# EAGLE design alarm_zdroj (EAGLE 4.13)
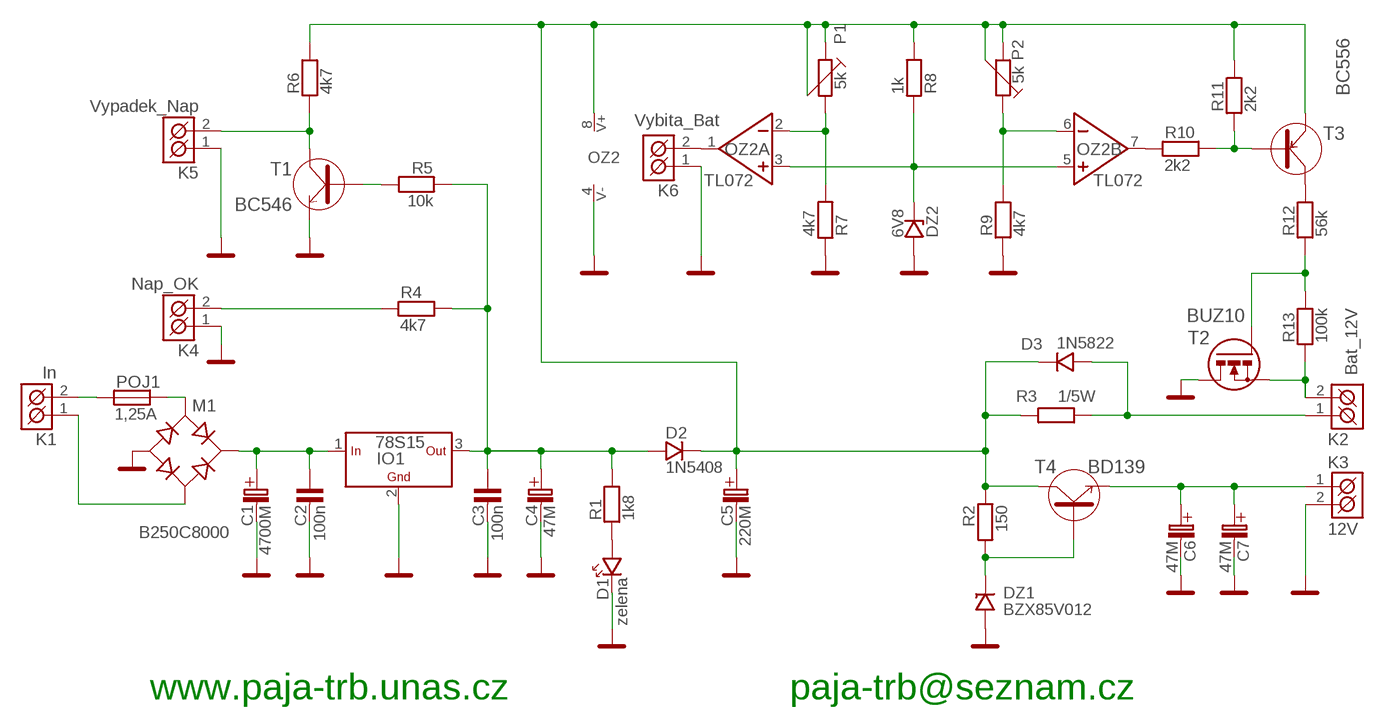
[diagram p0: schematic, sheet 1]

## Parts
C1  4700M  2200M/35V  [C_EL_7,5]
C2  100n  C-KERAMIK_5  [C-5]
C3  100n  C-KERAMIK_5  [C-5]
C4  47M  47M/25V  [C_EL_2]
C5  220M  220M/25V  [C_EL_3,5]
C6  47M  47M/25V  [C_EL_2]
C7  47M  47M/25V  [C_EL_2]
D1  zelena  LED_5  [LED_5]
D2  1N5408  [D-12,7]
D3  1N5822  1N5408  [D-12,7]
DZ1  BZX85V012  D-ZENEROVA_2W_BZY  [D-10]
DZ2  6V8  D-ZENEROVA_0,5W_BZX83V  [D-7,5]
IO1  78S15  78_STOJ_STOJ  [TO-220S]
K1  In  CZM_5/2  [CZM_5/2]
K2  Bat_12V  CZM_5/2  [CZM_5/2]
K3  12V  CZM_5/2  [CZM_5/2]
K4  Nap_OK  CZM_5/2  [CZM_5/2]
K5  Vypadek_Nap  CZM_5/2  [CZM_5/2]
K6  Vybita_Bat  CZM_5/2  [CZM_5/2]
M1  B250C8000  [DM_KBU]
OZ2  TL072  [DIL8]
P1  5k  PT-10_V-LEZ  [PT10V]
P2  5k  PT-10_V-LEZ  [PT10V]
POJ1  1,25A  PO_SHH  [POJ_SHH]
R1  1k8  R_7,5  [R-7,5]
R2  150  R_7,5  [R-7,5]
R3  1/5W  R__5W  [R-_5W]
R4  4k7  R_7,5  [R-7,5]
R5  10k  R_7,5  [R-7,5]
R6  4k7  R_7,5  [R-7,5]
R7  4k7  R_7,5  [R-7,5]
R8  1k  R_7,5  [R-7,5]
R9  4k7  R_7,5  [R-7,5]
R10  2k2  R_7,5  [R-7,5]
R11  2k2  R_7,5  [R-7,5]
R12  56k  R_7,5  [R-7,5]
R13  100k  R_7,5  [R-7,5]
T1  BC546  [TO-92]
T2  BUZ10  BUZ10_STOJ  [TO-220S]
T3  BC556  [TO-92]
T4  BD139  [TO-126S]

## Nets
12V: C6.C+(C_EL+) C7.C+(C_EL+) K3.1(K1) T4.1(E)
15V: C3.1 C4.C+(C_EL+) D2.A IO1.3(OUT) R1.2 R4.2 R5.1
+BAT: C5.C+(C_EL+) D2.K D3.K OZ2.8(NS:V+) P1.1 P1.3 P2.2 P2.3 R2.1 R3.1 R6.2 R8.2 R11.2 T3.3(E) T4.2(C)
GND: C1.C-(C_EL-) C2.2 C3.2 C4.C-(C_EL-) C5.C-(C_EL-) C6.C-(C_EL-) C7.C-(C_EL-) D1.K DZ1.A DZ2.A IO1.2(GND) K3.2(K2) K4.1(K1) K5.1(K1) K6.1(K1) M1.- OZ2.4(NS:V-) R7.1 R9.1 T1.3(E) T2.2(D)
GND_BAT: K2.2(K2) R13.1 T2.3(S)
N$1: K1.2(K2) POJ1.L1
N$2: K1.1(K1) M1.AC2
N$3: C1.C+(C_EL+) C2.1 IO1.1(IN) M1.+
N$4: D3.A K2.1(K1) R3.2
N$5: D1.A R1.1
N$6: R5.2 T1.2(B)
N$7: K4.2(K2) R4.1
N$8: K5.2(K2) R6.1 T1.1(C)
N$9: M1.AC1 POJ1.P1
N$10: DZ1.K R2.2 T4.3(B)
N$13: R12.1 R13.2 T2.1(G)
N$14: DZ2.K OZ2.3(A:NEIN+) OZ2.5(B:NEIN+) R8.1
N$15: OZ2.2(A:IN-) P1.2 R7.2
N$16: OZ2.7(B:VYSTUP) R10.1
N$17: K6.2(K2) OZ2.1(A:VYSTUP)
N$18: R10.2 R11.1 T3.2(B)
N$20: R12.2 T3.1(C)
N$22: OZ2.6(B:IN-) P2.1 R9.2

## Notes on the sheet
- www.paja-trb.unas.cz | paja-trb@seznam.cz

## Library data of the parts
C1 = #PaJa_C-el:2200M/35V
C2 C3 = #PaJa_13:C-KERAMIK: Kondenzator - keramicky
C4 C6 C7 = #PaJa_C-el:47M/25V
C5 = #PaJa_C-el:220M/25V
D1 = #PaJa_13:LED: LED - jednobarevna
D2 D3 = #PaJa_13:1N5408: Usmernovaci dioda - 3A, 1000V
DZ1 DZ2 = #PaJa_13:D-ZENEROVA: Zenerova dioda
IO1 = #PaJa_13:78??: Stabilizátor - 1A a 1,5A ?? - napeti => 05, 06, 08, 09, 12, 15, 18, 20, 24 => 1,5A ?? - napeti => 10, 12, 15, 18 => 1A
K1-K6 = #PaJa_14:CZM_5/2: Svorkovnice - roztec 5,08mm - dvojita
M1 = #PaJa_15:B250C8000: Diodovy mustek - 250V, 8A
OZ2 = #PaJa_14:TL072: OZ - JFET - 2x
P1 = #PaJa_13:PT-10: Trimr - 10,3mm
P2 = #PaJa_14:PT-10: Trimr - 10,3mm
POJ1 = #PaJa_14:PO_SHH: Pojistkove pouzdro
R1 R5-R8 = #PaJa_13:R: Rezistor
R2 R3 = #PaJa_15:R: Rezistor
R4 R9-R13 = #PaJa_14:R: Rezistor
T1 = #PaJa_13:BC546: Tranzistor NPN - Univerzalni NF - Ic=0,1A
T2 = #PaJa_14:BUZ10: N-Channel Enhancement MOSFET 50V; 20A; 0,080Ohm
T3 = #PaJa_14:BC556: Tranzistor PNP - Univerzalni NF - Ic=0,1A
T4 = #PaJa_15:BD139: Tranzistor NPN - Vykonovy - Ic=1,5A

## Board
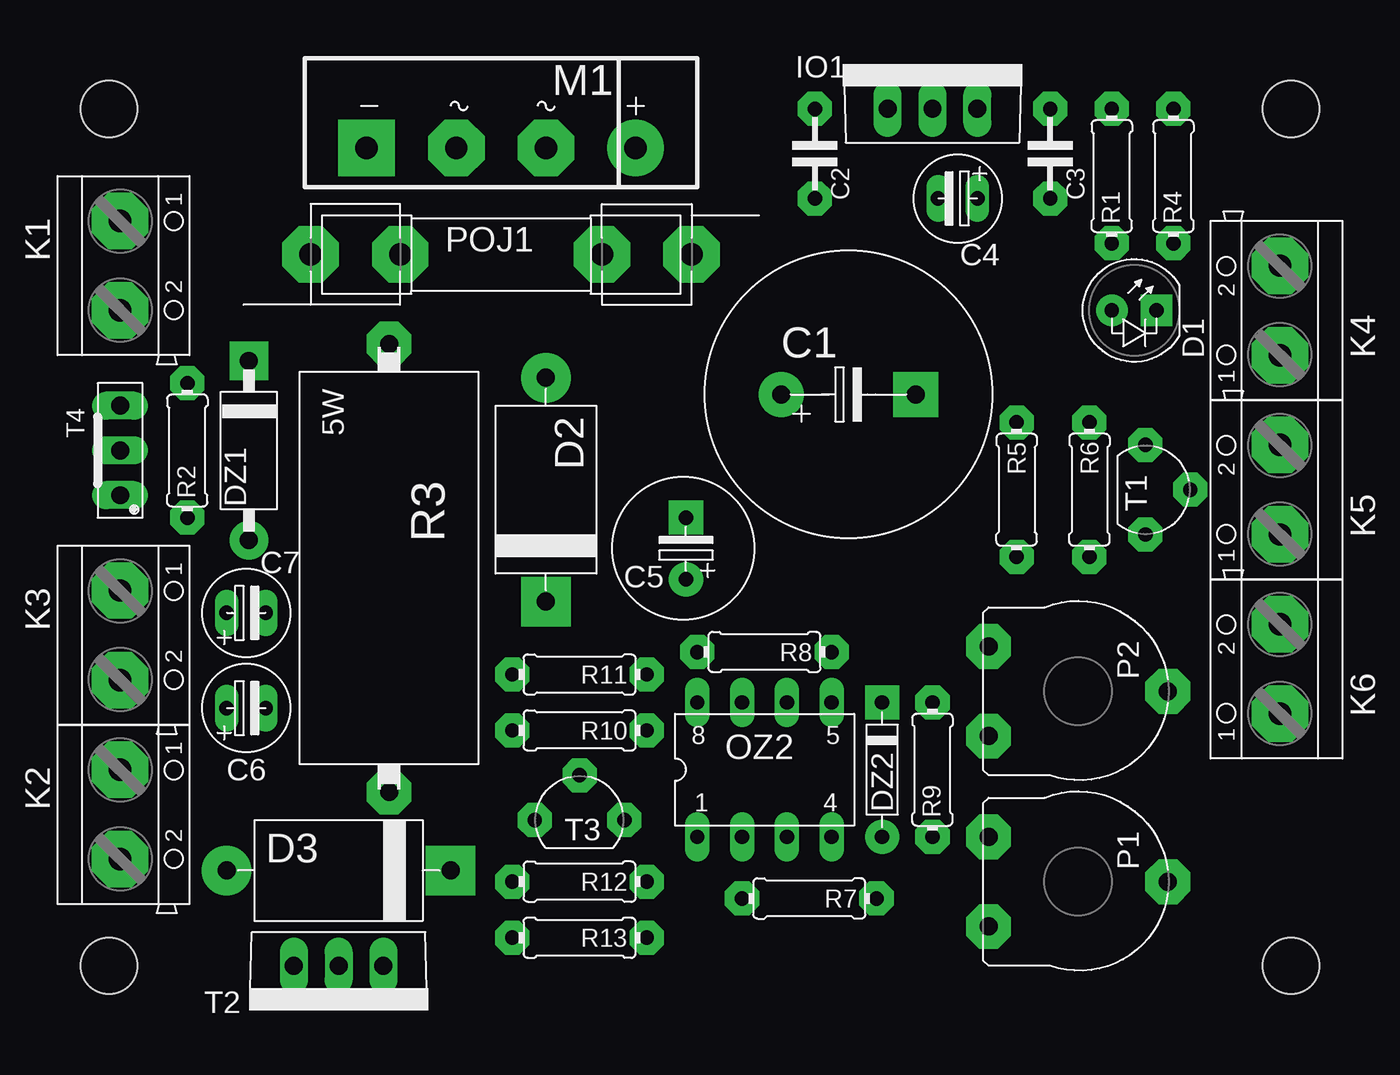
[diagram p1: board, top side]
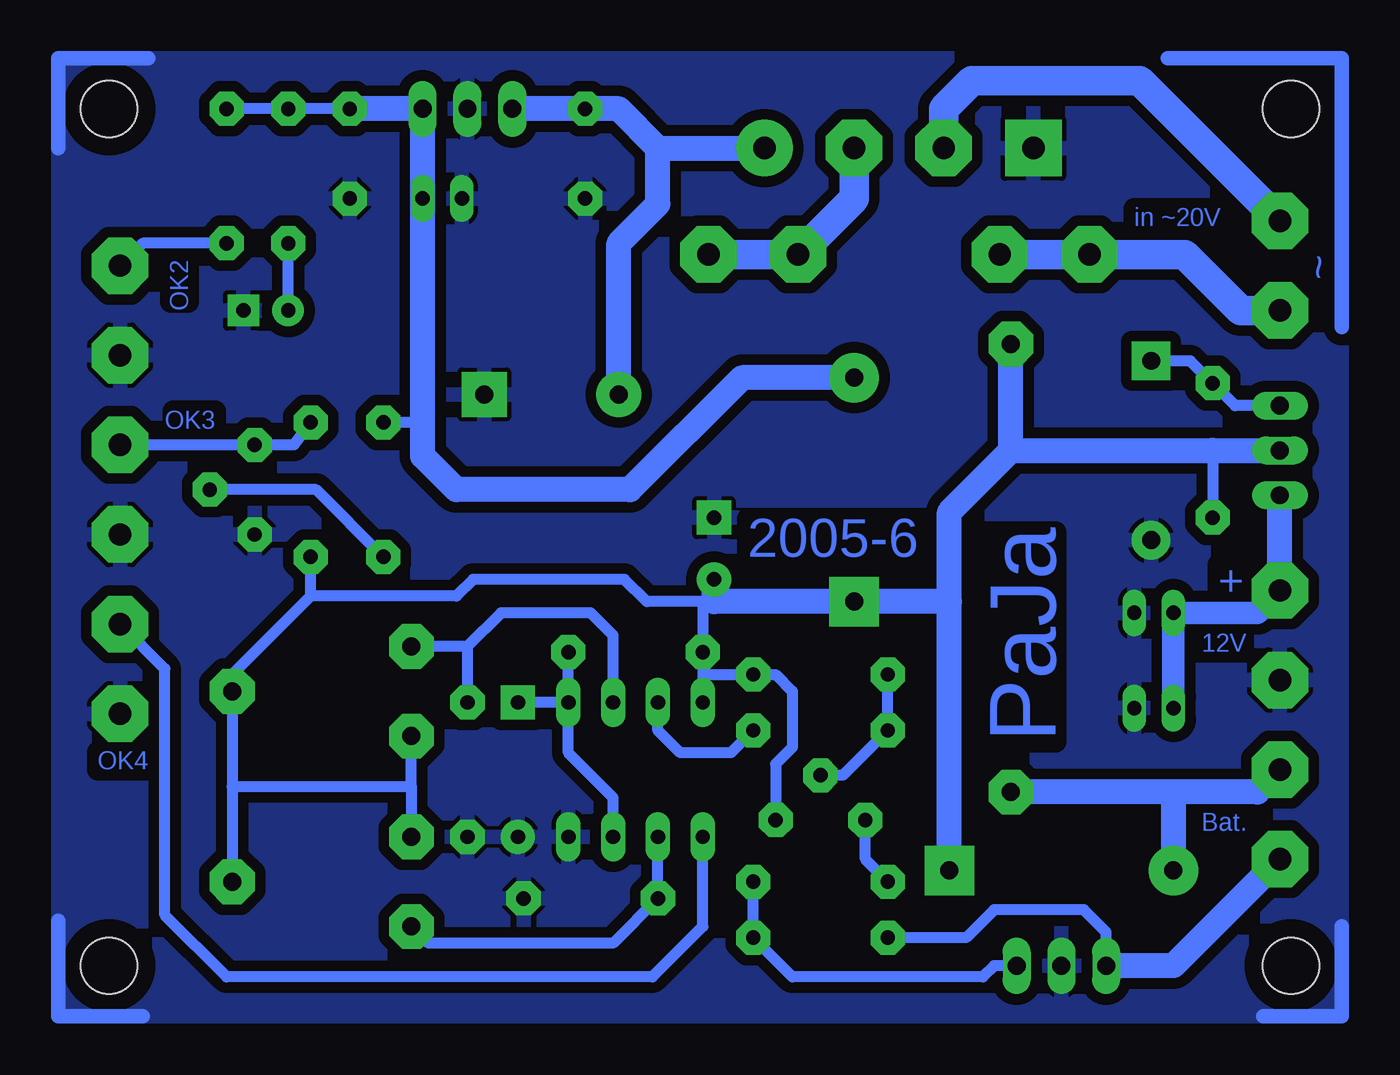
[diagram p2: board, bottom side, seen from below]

No outline drawn. Coordinates in mm, seen from the top.
Copper layers (1*16): Top 0.035mm / dielectric 1.5mm / Bottom 0.035mm
Design rules "default": minimum track width 10mil, minimum drill 24mil, track to track 8mil, track to pad 8mil, pad to pad 8mil, via to via 8mil, smd to smd 8mil, copper to edge 40mil, drill to drill 8mil, minimum pad ring 10mil, minimum via ring 8mil, stop-mask expansion 4mil, vias tented up to drill 0mil, thermal gap 10mil
Holes 3.2 mm at 6.67,13.02 6.67,61.59 73.66,61.59 73.66,13.02

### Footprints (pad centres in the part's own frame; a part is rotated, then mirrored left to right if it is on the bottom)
C_EL_7,5 = drill 1.016 pad 2.54 round: C+ -3.81,0 | drill 1.016 pad 2.54 square: C- 3.81,0
C-5 = drill 0.813 pad 1.93 octagon: 1 -2.54,0; 2 2.54,0
C_EL_2 = drill 0.813 pad 1.27 long: C+ 0,0; C- 2.223,0
C_EL_3,5 = drill 0.813 pad 1.93 round: C+ 0,0 | drill 0.813 pad 1.93 square: C- 3.493,0
LED_5 = drill 0.813 pad 1.778 round: A -1.27,0 | drill 0.813 pad 1.778 square: K 1.27,0
D-12,7 = drill 1.016 pad 2.8 round: A -6.35,0 | drill 1.016 pad 2.8 square: K 6.35,0
D-10 = drill 1.016 pad 2.184 round: A -5.08,0 | drill 1.016 pad 2.184 square: K 5.08,0
D-7,5 = drill 0.813 pad 1.93 round: A -3.81,0 | drill 0.813 pad 1.93 square: K 3.81,0
TO-220S = drill 1.016 pad 1.6 long: 1 -2.54,0; 2 0,0; 3 2.54,0
CZM_5/2 = drill 1.27 pad 3.2 octagon: 1 -2.54,0; 2 2.54,0
DM_KBU = drill 1.27 pad 3.2 round: + -7.62,2.857 | drill 1.27 pad 3.2 square: - 7.62,2.857 | drill 1.27 pad 3.2 octagon: AC1 -2.54,2.857; AC2 2.54,2.857
DIL8 = drill 0.813 pad 1.4 long: 1 -3.81,-3.81; 2 -1.27,-3.81; 3 1.27,-3.81; 4 3.81,-3.81; 5 3.81,3.81; 6 1.27,3.81; 7 -1.27,3.81; 8 -3.81,3.81
PT10V = drill 1.016 pad 2.54 octagon: 1 -2.54,-5.08; 2 2.54,-5.08; 3 0,5.08
POJ_SHH = drill 1.27 pad 3.2 octagon: L1 -10.795,0; L2 -5.715,0; P1 10.795,0; P2 5.715,0
R-7,5 = drill 0.813 pad 1.93 octagon: 1 -3.81,0; 2 3.81,0
R-_5W = drill 1.016 pad 2.54 octagon: 1 -12.7,0; 2 12.7,0
TO-92 = drill 0.813 pad 1.93 octagon: 1 0,2.54; 2 2.54,0; 3 0,-2.54
TO-126S = drill 1.016 pad 1.6 long: 1 -2.54,0; 2 0,0; 3 2.54,0

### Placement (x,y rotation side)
C1  48.58,45.4 0 top
C2  46.67,59.05 270 top
C3  60.01,59.05 270 top
C4  55.88,56.52 180 top
C5  39.37,34.92 90 top
C6  13.34,27.62 0 top
C7  13.34,33.02 0 top
D1  64.77,50.16 0 top
D2  31.43,40.01 270 top
D3  19.68,18.41 0 top
DZ1  14.61,42.23 90 top
DZ2  50.48,24.13 90 top
IO1  53.34,61.59 0 top
K1  7.3,52.7 270 top
K2  7.3,21.59 270 top
K3  7.3,31.75 270 top
K4  73.03,50.16 90 top
K5  73.03,40.01 90 top
K6  73.03,29.84 90 top
M1  28.89,62.23 180 top
OZ2  43.81,24.13 0 top
P1  61.59,17.78 270 top
P2  61.59,28.57 270 top
POJ1  28.89,53.34 0 top
R1  63.5,57.78 90 top
R2  11.11,42.23 90 top
R3  22.54,35.56 270 top
R4  66.99,57.78 90 top
R5  58.1,40.01 270 top
R6  62.23,40.01 270 top
R7  46.35,16.83 180 top
R8  43.81,30.8 180 top
R9  53.34,24.13 90 top
R10  33.34,26.35 180 top
R11  33.34,29.53 0 top
R12  33.34,17.78 180 top
R13  33.34,14.61 0 top
T1  65.41,40.01 0 top
T2  19.68,13.02 180 top
T3  33.34,21.27 90 top
T4  7.3,42.23 90 top

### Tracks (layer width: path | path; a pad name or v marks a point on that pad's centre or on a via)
12V
  Bottom 1.27: C6.C+ C7.C+ 8.57,33.02 K3.1
  Bottom 1.422: K3.1 T4.1
15V
  Bottom 0.61: R4.2 R1.2 C3.1 | 55.88,43.81 R5.1
  Bottom 1.422: C3.1 IO1.3 C4.C+ 55.88,43.81 55.88,41.91 53.98,40.01 44.13,40.01 37.78,46.35 D2.A
+BAT
  Bottom 0.61: 66.67,23.18 P2.3 66.67,29.53 62.23,33.97 | 66.67,23.18 P1.3 | 66.67,23.18 56.52,23.18 | 56.52,23.18 P2.2 | 56.52,23.18 P1.1 | T3.3 35.88,24.45 34.92,25.4 34.92,28.57 35.88,29.53 R11.2 40.01,29.53 | 62.23,33.97 53.98,33.97 53.02,34.92 44.45,34.92 43.18,33.66 40.01,33.66 | 62.23,33.97 R6.2 | 11.11,42.23 R2.1 | 39.37,33.66 40.01,33.66 | 40.01,33.66 R8.2 40.01,29.53 | 40.01,29.53 OZ2.8
  Bottom 1.422: 22.54,42.23 11.11,42.23 T4.2 | 22.54,42.23 R3.1 | 26.04,33.66 D2.K 39.37,33.66 C5.C+ | D3.K 26.04,33.66 | 26.04,33.66 26.04,38.73 22.54,42.23
GND
  Bottom 0.813: 71.44,64.45 76.52,64.45 76.52,59.37 | 71.75,10.16 76.52,10.16 76.52,15.56 | 3.81,15.24 3.81,10.16 8.26,10.16
  pour Bottom (isolate 0.61): 3.81,64.45 3.81,10.16 76.52,10.16 76.52,64.45
GND_BAT
  Bottom 0.61: T2.3 17.14,14.92 18.41,16.19 23.5,16.19 25.08,14.61 R13.1
  Bottom 1.422: K2.2 13.34,13.02 T2.3
N$1
  Bottom 1.676: K1.2 9.53,50.16 12.7,53.34 POJ1.L1 23.18,53.34
N$2
  Bottom 1.676: K1.1 15.24,63.18 24.77,63.18 26.35,61.59 M1.AC2
N$3
  Bottom 1.422: IO1.1 C2.1 44.77,61.59 42.55,59.37 | 42.55,59.37 M1.+ | C1.C+ 44.77,53.98 42.55,56.2 42.55,59.37
N$4
  Bottom 1.422: 13.34,22.86 R3.2 | 13.34,22.86 D3.A | K2.1 8.57,22.86 13.34,22.86
N$5
  Bottom 0.61: D1.A R1.1
N$6
  Bottom 0.61: R5.2 61.91,40.01 T1.2
N$7
  Bottom 0.61: R4.1 71.75,53.98 K4.2
N$8
  Bottom 0.61: R6.1 63.18,42.55 T1.1 K5.2
N$9
  Bottom 1.676: POJ1.P1 34.61,53.34 31.43,56.52 M1.AC1
N$10
  Bottom 0.61: T4.3 9.84,44.77 R2.2 12.38,47.31 DZ1.K
N$11
  Bottom 0.813: 13.65,64.45 3.81,64.45 3.81,49.21
N$13
  Bottom 0.61: T2.1 23.5,13.02 24.13,12.38 34.92,12.38 R13.2 R12.1
N$14
  Bottom 0.61: OZ2.5 47.62,25.08 45.09,22.54 OZ2.3 | OZ2.5 R8.1 | OZ2.5 DZ2.K
N$15
  Bottom 0.61: P1.2 55.56,14.29 45.09,14.29 R7.2 OZ2.2
N$16
  Bottom 0.61: OZ2.7 42.55,26.35 41.27,25.08 38.42,25.08 R10.1
N$17
  Bottom 0.61: OZ2.1 40.01,15.24 42.86,12.38 66.99,12.38 70.48,15.88 70.48,29.84 K6.2
N$18
  Bottom 0.61: R11.1 R10.2 32.07,23.81 T3.2
N$20
  Bottom 0.61: T3.1 30.8,19.05 R12.2
N$22
  Bottom 0.61: OZ2.6 45.09,31.75 46.35,33.02 51.44,33.02 53.34,31.11 | 53.34,31.11 R9.2 | 53.34,31.11 P2.1

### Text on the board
Bottom: in ~20V | ~ | OK2 | OK3 | 2005-6 | + | 12V | PaJa | OK4 | Bat.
